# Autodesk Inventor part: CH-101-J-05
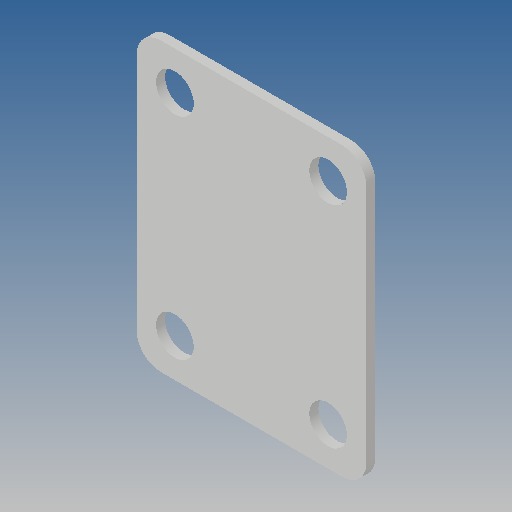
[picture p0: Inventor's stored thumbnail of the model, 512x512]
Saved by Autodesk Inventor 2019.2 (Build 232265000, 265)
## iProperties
Created: 2012-09
Part Number: CH-101-J-05
Material: Ogólny
Document SubType Name: Modeling
Designer: CADENGINEERING4
Density: 1 g/cm^3
Appearance: Domyślna
Author: CADENGINEERING4
Revision Number: ÈÎºÎ
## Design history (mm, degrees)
feature "À­Éì1"
node "Bryła1"
